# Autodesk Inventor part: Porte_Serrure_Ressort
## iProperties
Created: 2009-01
Part Number: Porte_Serrure_Ressort
Document SubType Name: Modeling
Designer: claivier
Author: claivier
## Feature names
1. Base1
